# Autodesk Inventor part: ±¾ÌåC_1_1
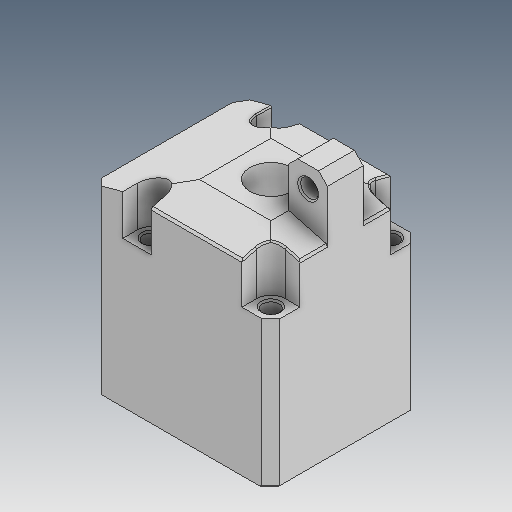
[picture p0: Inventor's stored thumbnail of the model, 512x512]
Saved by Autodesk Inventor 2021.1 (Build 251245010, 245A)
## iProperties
Created: 2019-04
Part Number: ±¾ÌåC_1_1
Material: Ogólny
Document SubType Name: Modeling
Designer: user
Density: 1 g/cm^3
Appearance: Domyślna
Author: user
Revision Number: ÈÎºÎ
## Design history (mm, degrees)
feature "ÊäÈë1"
feature "ÊäÈë2"
node "Bryła1"
node "Bryła2"
